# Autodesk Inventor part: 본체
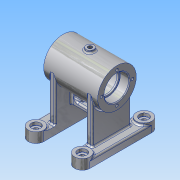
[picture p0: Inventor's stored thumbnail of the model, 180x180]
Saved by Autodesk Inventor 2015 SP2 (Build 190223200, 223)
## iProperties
Created: 2015-11
Part Number: 본체
Material: 알루미늄 6061
Document SubType Name: Modeling
Designer: AMC
Density: 2.7 g/cm^3
Appearance: 알루미늄 - 평지
Mass: 356.095 g
Surface Area: 461.667 cm^2
Volume: 131.887 cm^3
Author: AMC
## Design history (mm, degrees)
node "작업 평면1"
sketch "스케치2"
  geometry: L1 (-30, -40)-(-30, 40); L2 (-20, -40)-(-20, 40); L3 (-40, 40)-(-40, -40); L4 (0, -70)-(0, 70) reference; L5 (30, -40)-(30, 40); L6 (20, -40)-(20, 40); L7 (40, 40)-(40, -40); A1 r 10 centre (-30, -40) between (-40, -40) and (-20, -40); A2 r 10 centre (-30, 40) between (-20, 40) and (-40, 40); A3 r 10 centre (30, -40) between (20, -40) and (40, -40); A4 r 10 centre (30, 40) between (40, 40) and (20, 40); 5 further points
  constraints: 16 end point, 8 point on circle, 7 symmetric about line, 4 centre point, 4 tangent, 1 midpoint, 1 parallel, 1 vertical, 2 other
  dimensions: "d4" = 20 diameter of A2; "d5" = 80 distance of L1.end L1.start; "d18" = 40 distance between parallel lines of L4 L3
extrude "돌출2" join sketch "스케치2" distance "d7" = 10; taper "d8" = 0 deg
sketch "스케치4"
  geometry: L1 (40, -40)-(40, 40) reference; L2 (-56, 0)-(56, 0) reference; C1 r 10 at (30, -40); C2 r 10 at (30, 40); C3 r 10 at (-30, -40); C4 r 10 at (-30, 40); A1 r 10 centre (30, -40) between (20, -40) and (40, -40) reference; 1 further point
  constraints: 4 centre point, 1 coincident, 1 concentric, 1 horizontal, 1 vertical, 6 other
  dimensions: "d22" = 80 distance of C1.centre C2.centre; "d25" = 60 distance of C1.centre C3.centre
extrude "돌출3" join sketch "스케치4" distance "d28" = 3; taper "d29" = 0 deg
sketch "스케치5"
  geometry: L1 (-20, -25)-(-28, -25); L2 (-28, -25)-(-28, 25); L3 (-28, 25)-(-20, 25); L4 (-20, 25)-(-20, -25); L5 (-20, -40)-(-20, 40) reference; L6 (-56, 0)-(56, 0) reference; L7 (0, -70)-(0, 70) reference; L8 (20, -25)-(28, -25); L9 (28, -25)-(28, 25); L10 (28, 25)-(20, 25); L11 (20, 25)-(20, -25); 1 further point
  constraints: 16 end point, 4 symmetric about line, 2 parallel, 1 collinear, 1 horizontal, 1 perpendicular
  dimensions: "d30" = 8 distance of L2.end L3.end; "d31" = 50 distance of L1.end L2.end; "d32" = 25 distance between parallel lines of L6 L3
extrude "돌출4" join sketch "스케치5" distance "d33" = 58; taper "d34" = 0 deg
sketch "스케치6"
  geometry: C1 r 25 at (0, 0); 1 further point
  constraints: 1 centre point, 1 coincident
  dimensions: "d35" = 50 diameter of C1
extrude "돌출5" join sketch "스케치6" stored distance "d36" = 70; taper "d37" = 0 deg
hole "구멍1" diameter "d40" = 6; stored, may be unused: countersink angle "d44" = 82 deg, drill point angle "d46" = 0 deg; dims "d41" = 6.35, "d42" = 12, "d43" = 4, "d45" = 4, "d47" = 10, "d48" = 10
chamfer "모따기1" distance "d49" = 1; stored, may be unused: second distance "d50" = 2, angle "d51" = 45 deg
fillet "모깎기1" dims "d79" = 0.3
sketch "스케치7"
  geometry: L1 (0, 19.725)-(-5, 19.725); L2 (-5, 19.725)-(-5, 28); L3 (-5, 28)-(0, 28); L4 (0, 28)-(0, 19.725); L5 (-70, 0)-(70, 0) reference; L6 (0, -87.2)-(0, 47.2) reference; L7 (6.17, -20.687)-(9.67, -26.749); L8 (9.67, -26.749)-(14, -24.249); L9 (14, -24.249)-(10.5, -18.187); L10 (10.5, -18.187)-(6.17, -20.687); L11 (0, 0)-(14, -24.249); C1 r 25 at (0, 0) reference; 1 further point
  constraints: 18 end point, 3 parallel, 3 perpendicular, 2 collinear, 1 horizontal
  dimensions: "d58" = 5 distance of L2.end L3.end; "d59" = 28 distance from line of L11.start L3; "d60" = 8.27482 distance between parallel lines of L3 L1; "d62" = 5 distance between parallel lines of L9 L7; "d63" = 28 distance from line of point (0, 0) L8; "d65" = 7 distance between parallel lines of L8 L10; "d67" = 30 deg angle of L11 L6
revolve "회전1" stored, may be unused: angle "d68" = 90 deg
revolve "회전2" stored, may be unused: angle "d69" = 90 deg
sketch "스케치8"
  geometry: L1 (21.881, -45)-(-23.319, -45); L2 (-23.319, -45)-(-23.319, -14.736); L3 (-23.319, -14.736)-(21.881, -14.736); L4 (21.881, -14.736)-(21.881, -45); L5 (21.881, -45)-(-23.319, -14.736); L6 (-23.319, -45)-(21.881, -14.736); L7 (35, -25)-(-35, -25) reference; L8 (11.5, -35)-(-11.5, -35); L9 (11.5, -31.5)-(-11.5, -31.5); L10 (-11.5, -38.5)-(11.5, -38.5); L11 (0, -87.2)-(0, 47.2) reference; L12 (-40, -68)-(-20, -68) reference; A1 r 3.5 centre (11.5, -35) between (11.5, -38.5) and (11.5, -31.5); A2 r 3.5 centre (-11.5, -35) between (-11.5, -31.5) and (-11.5, -38.5); 3 further points
  constraints: 20 end point, 4 point on circle, 4 tangent, 3 midpoint, 3 parallel, 2 centre point, 2 horizontal, 1 perpendicular, 1 point on line
  dimensions: "d70" = 20 distance between parallel lines of L1 L7; "d71" = 23 distance of L8.end L8.start; "d72" = 33 distance between parallel lines of L12 L8; "d73" = 7 distance between parallel lines of L10 L9
extrude "돌출6" join sketch "스케치8" stored distance "d74" = 8; taper "d75" = 0 deg
fillet "모깎기2" dims "d80" = 0.3
fillet "모깎기3" dims "d81" = 2
hole "구멍2" diameter "d89" = 28; stored, may be unused: countersink angle "d93" = 82 deg, drill point angle "d95" = 0 deg; dims "d90" = 6.35, "d91" = 32, "d92" = 12, "d94" = 15, "d114" = 10, "d115" = 10
hole "구멍3" diameter "d100" = 28; stored, may be unused: countersink angle "d104" = 82 deg, drill point angle "d106" = 0 deg; dims "d101" = 6.35, "d102" = 32, "d103" = 12, "d105" = 15, "d112" = 10, "d113" = 10
sketch "스케치9"
  geometry: L1 (56.01, 0)-(-56.01, 0) reference; L2 (0, -87.2)-(0, 47.2) reference; L3 (-21, 0)-(21, 0); L4 (21, 0)-(21, 21); L5 (21, 21)-(-21, 21); L6 (-21, 21)-(-21, 0)
  constraints: 8 end point, 2 parallel, 1 horizontal, 1 perpendicular, 1 point on line
  dimensions: "d83" = 42 distance between parallel lines of L4 L6; "d84" = 21 distance between parallel lines of L1 L5; "d85" = 21 distance between parallel lines of L2 L4
revolve "회전3" sketch "스케치9" stored, may be unused: angle "d86" = 90 deg
fillet "모깎기4" dims "d107" = 0.3
fillet "모깎기5" dims "d108" = 3
chamfer "모따기3" distance "d109" = 1; stored, may be unused: second distance "d110" = 2, angle "d111" = 45 deg
sketch "스케치10"
  geometry: L1 (87.2, 0)-(-47.2, 0) reference; L2 (0, -70)-(0, 70) reference; 1 further point
  constraints: 1 point on line
  dimensions: "d116" = 20 distance from line of L2 point (-20, 0)
hole "구멍4" sketch "스케치10" at (-20, 0) diameter "d117" = 3.459; stored, may be unused: countersink angle "d121" = 82 deg, drill point angle "d123" = 118 deg; dims "d118" = 8, "d119" = 40, "d120" = 12, "d122" = 10
hole "구멍5" diameter "d129" = 5.188; stored, may be unused: countersink angle "d133" = 82 deg, drill point angle "d135" = 0 deg; dims "d127" = 10, "d128" = 10, "d130" = 12, "d131" = 40, "d132" = 12, "d134" = 12
hole "구멍6" diameter "d138" = 5.188; stored, may be unused: countersink angle "d142" = 82 deg, drill point angle "d144" = 0 deg; dims "d136" = 10, "d137" = 10, "d139" = 12, "d140" = 40, "d141" = 12, "d143" = 12
node "작업 평면3"
sketch "스케치15"
  geometry: L1 (-17.371, -4.947)-(17.371, -4.947); L2 (17.371, -4.947)-(17.371, 4.947); L3 (17.371, 4.947)-(-17.371, 4.947); L4 (-17.371, 4.947)-(-17.371, -4.947); L5 (-17.371, -4.947)-(17.371, 4.947); L6 (-17.371, 4.947)-(17.371, -4.947); L7 (-56.01, 0)-(56.01, 0) reference; L8 (0, -87.2)-(0, 47.2) reference; 2 further points
  constraints: 4 end point, 1 midpoint, 2 other
  dimensions: "d148" = 0 distance from line of L8 point (0, 0); "d149" = 0 distance from line of L7 point (0, 0)
feature "엠보싱1" sketch "스케치15" dims "d150" = 0.5, "d151" = 0
node "솔리드1"
pattern_linear "직사각형 패턴1" dims "d54" = 80
pattern_circular "원형 패턴1" dims angle "d125" = 360 deg
mirror "대칭1"
other parameters: "d3" = -68, "d147" = -14.75
